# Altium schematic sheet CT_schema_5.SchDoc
size 334 x 183 mm
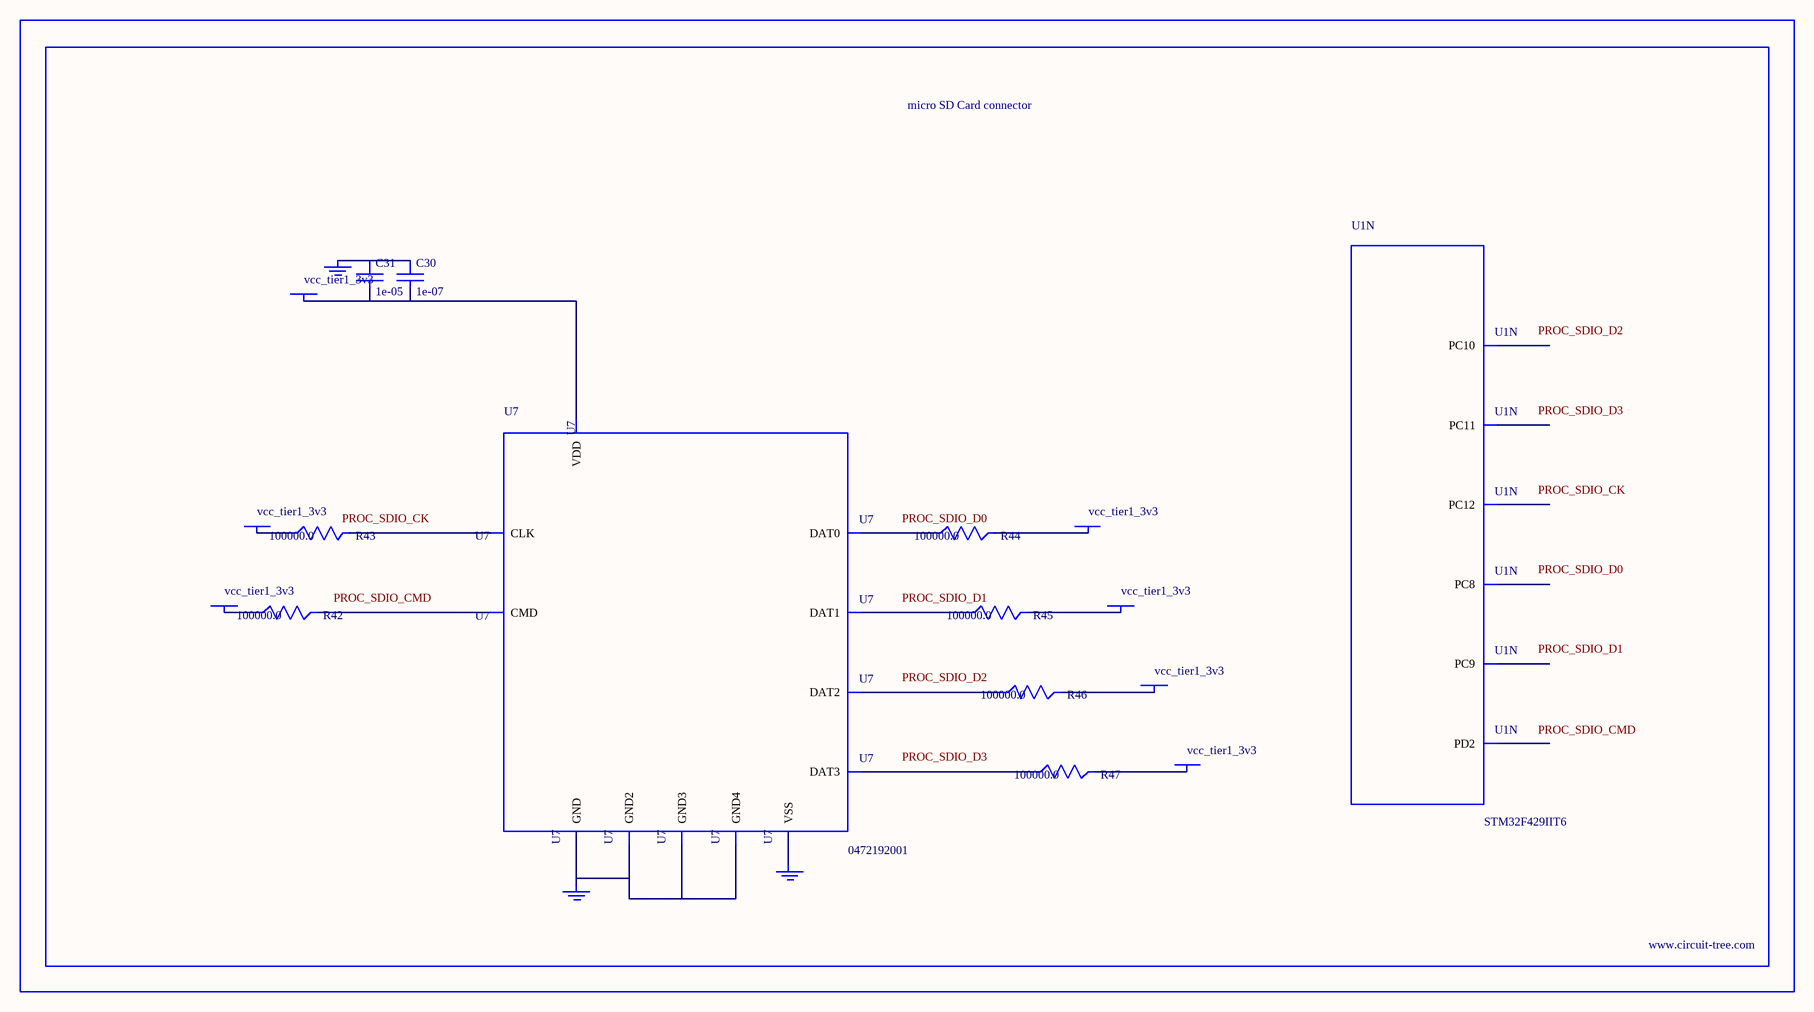
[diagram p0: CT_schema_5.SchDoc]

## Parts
BORDER4  (no value)
C30  1e-07  [C0402]
C31  1e-05  [C0805]
GND_INSTANCE_4_0  (no value)
GND_INSTANCE_4_1  (no value)
GND_INSTANCE_4_2  (no value)
POWER_INSTANCE_4_0  vcc_tier1_3v3
POWER_INSTANCE_4_1  vcc_tier1_3v3
POWER_INSTANCE_4_2  vcc_tier1_3v3
POWER_INSTANCE_4_3  vcc_tier1_3v3
POWER_INSTANCE_4_4  vcc_tier1_3v3
POWER_INSTANCE_4_5  vcc_tier1_3v3
POWER_INSTANCE_4_6  vcc_tier1_3v3
R42  100000.0  [R0603]
R43  100000.0  [R0603]
R44  100000.0  [R0603]
R45  100000.0  [R0603]
R46  100000.0  [R0603]
R47  100000.0  [R0603]
U1  STM32F429IIT6  [LQFP176]  (part N of 15)
U7  0472192001  [MOLEX_47219-2001]

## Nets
NetC30_1: C30.1 C31.1 GND_INSTANCE_4_0.0(GND)
NetC30_2: C30.2 C31.2 POWER_INSTANCE_4_3.0(PWR) U7.4(VDD)
NetGND_INSTANCE_4_1_0: GND_INSTANCE_4_1.0(GND) U7.6(VSS)
NetGND_INSTANCE_4_2_0: GND_INSTANCE_4_2.0(GND) U7.G1(GND) U7.G2(GND2) U7.G3(GND3) U7.G4(GND4)
NetPOWER_INSTANCE_4_0_0: POWER_INSTANCE_4_0.0(PWR) R46.2
NetPOWER_INSTANCE_4_1_0: POWER_INSTANCE_4_1.0(PWR) R47.2
NetPOWER_INSTANCE_4_2_0: POWER_INSTANCE_4_2.0(PWR) R42.1
NetPOWER_INSTANCE_4_4_0: POWER_INSTANCE_4_4.0(PWR) R43.1
NetPOWER_INSTANCE_4_5_0: POWER_INSTANCE_4_5.0(PWR) R44.2
NetPOWER_INSTANCE_4_6_0: POWER_INSTANCE_4_6.0(PWR) R45.2
NetR42_2: R42.2 U7.3(CMD)
NetR43_2: R43.2 U7.5(CLK)
NetR44_1: R44.1 U7.7(DAT0)
NetR45_1: R45.1 U7.8(DAT1)
NetR46_1: R46.1 U7.1(DAT2)
NetR47_1: R47.1 U7.2(DAT3)

Not connected (* = marked no-connect by the designer): U1 117(PC8) 118(PC9) 139(PC10) 140(PC11) 141(PC12) 144(PD2)

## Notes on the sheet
- Labels drawn without touching a wire or pin: PROC_SDIO_CK, PROC_SDIO_CMD, PROC_SDIO_D0, PROC_SDIO_D1, PROC_SDIO_D2, PROC_SDIO_D3

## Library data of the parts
BORDER4 = BORDER_PAGE4
C30 = C0402C104K3RACTU
C31 = C0805C106K8RACTU
GND_INSTANCE_4_0-GND_INSTANCE_4_2 = GND
POWER_INSTANCE_4_0-POWER_INSTANCE_4_6 = PWR
R42-R47 = RC0603JR-07100KL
